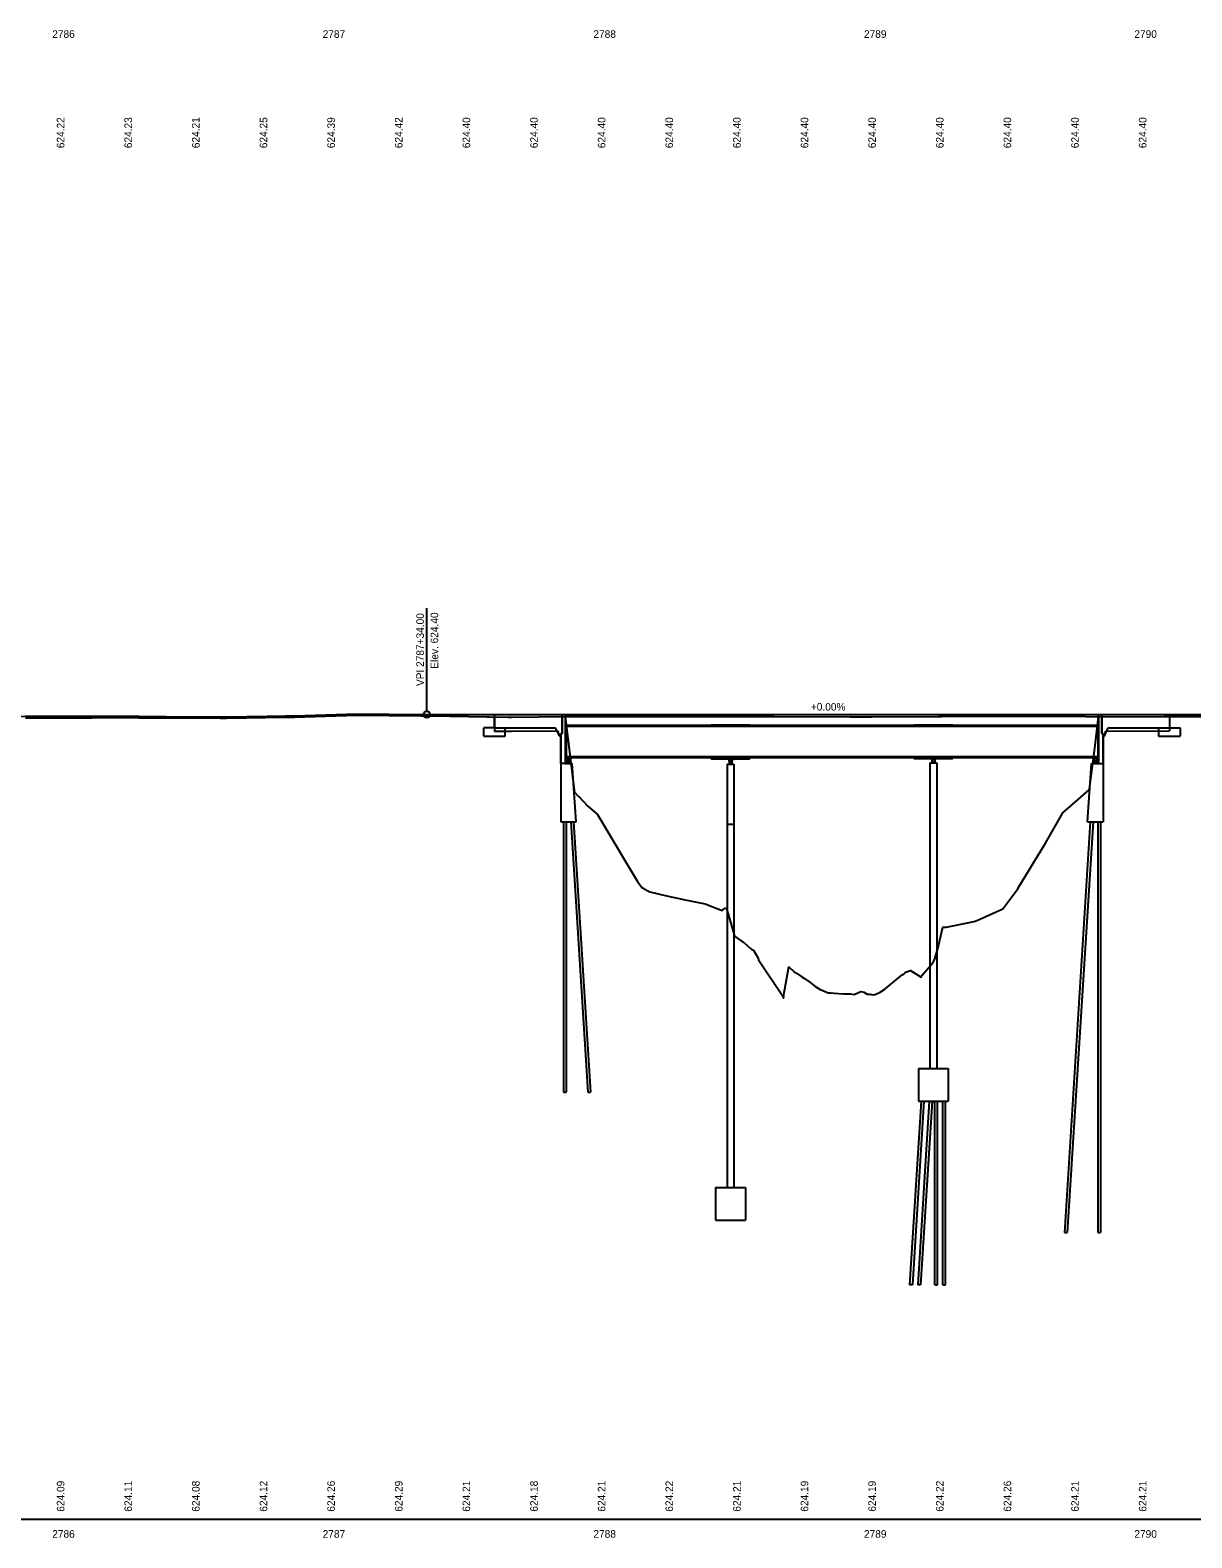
# Model space of a CAD drawing. Extents: x 2376379 to 2383101, y 559608 to 561720.
# Drawn here: x 2379153 to 2379582, y 560612 to 561170 of the extents above; entities that cross this region are included whole.
import ezdxf

# ---------------------------------------------------------------- set-up
doc = ezdxf.new("R2010")
doc.units = 0
for name, color, linetype in [('AP_P_Airside', 7, 'Continuous'), ('BR_X_SV_Abut', 7, 'Continuous'), ('BR_X_SV_Shot_Marker', 7, 'Continuous'), ('DR_X_Ditch', 7, 'Continuous'), ('DR_X_Erosion_Control', 7, 'Continuous'), ('DR_X_Storm_Sewer', 7, 'Continuous'), ('DR_X_Text', 7, 'Continuous'), ('DT_X_Terrain_Ground_Line', 7, 'Continuous'), ('PV_X_Driveway', 7, 'Continuous'), ('SC_Scratch1', 7, 'Continuous'), ('SV_X_Control_Cells_Found', 7, 'Continuous'), ('SV_X_Text', 7, 'Continuous'), ('UT_X_Overhead_Electric', 7, 'Continuous')]:
    doc.layers.add(name, color=color, linetype=linetype)

msp = doc.modelspace()

# ---------------------------------------------------------------- linework, layer by layer
at = {"layer": 'AP_P_Airside'}
msp.add_line((2379299.62, 560918.13), (2379299.62, 560956.2), dxfattribs=at)
msp.add_circle((2379299.62, 560916.92), 1.21, dxfattribs=at)
at = {"layer": 'BR_X_SV_Abut'}
for p, q in [((2379351.45, 560900.73), (2379351.45, 560899.73)), ((2379352.28, 560900.73), (2379351.45, 560900.73)), ((2379352.28, 560900.73), (2379352.28, 560899.73)), ((2379411.28, 560900.51), (2379411.28, 560899.68)), ((2379412.45, 560900.51), (2379411.28, 560900.51)), ((2379412.45, 560900.51), (2379412.45, 560899.68)), ((2379486.27, 560900.66), (2379486.27, 560900.16)), ((2379487.44, 560900.66), (2379486.27, 560900.66)), ((2379487.44, 560900.66), (2379487.44, 560900.16)), ((2379546.44, 560900.73), (2379546.44, 560899.73)), ((2379547.27, 560900.73), (2379546.44, 560900.73)), ((2379547.27, 560900.73), (2379547.27, 560899.73)), ((2379352.28, 560899.73), (2379351.45, 560899.73)), ((2379351.49, 560899.73), (2379351.49, 560898.84)), ((2379352.24, 560898.84), (2379351.49, 560898.84)), ((2379352.24, 560899.73), (2379352.24, 560898.84)), ((2379412.45, 560899.68), (2379411.28, 560899.68)), ((2379411.33, 560899.68), (2379411.33, 560898.52)), ((2379412.41, 560898.52), (2379411.33, 560898.52)), ((2379412.41, 560899.68), (2379412.41, 560898.52)), ((2379487.44, 560900.16), (2379486.27, 560900.16)), ((2379486.32, 560900.16), (2379486.32, 560899)), ((2379487.4, 560899), (2379486.32, 560899)), ((2379487.4, 560900.16), (2379487.4, 560899)), ((2379547.27, 560899.73), (2379546.44, 560899.73)), ((2379546.48, 560899.73), (2379546.48, 560898.84)), ((2379547.23, 560898.84), (2379546.48, 560898.84)), ((2379547.23, 560899.73), (2379547.23, 560898.84))]:
    msp.add_line(p, q, dxfattribs=at)
at = {"layer": 'DR_X_Ditch'}
for p, q in [((2379351.12, 560912.99), (2379351.12, 560900.99)), ((2379351.12, 560912.99), (2379547.62, 560912.99)), ((2379351.12, 560912.65), (2379547.62, 560912.65)), ((2379404.7, 560912.99), (2379404.7, 560913.14)), ((2379404.7, 560913.14), (2379419.03, 560913.14)), ((2379404.7, 560912.99), (2379404.7, 560913.14)), ((2379419.03, 560912.99), (2379419.03, 560913.14)), ((2379419.03, 560912.99), (2379419.03, 560913.14)), ((2379479.69, 560913.14), (2379494.02, 560913.14)), ((2379479.69, 560912.99), (2379479.69, 560913.14)), ((2379494.02, 560912.99), (2379494.02, 560913.14)), ((2379547.62, 560912.99), (2379547.62, 560900.99)), ((2379351.12, 560901.33), (2379547.62, 560901.33)), ((2379351.12, 560900.99), (2379547.62, 560900.99)), ((2379404.7, 560900.82), (2379404.7, 560900.99)), ((2379404.7, 560900.82), (2379419.03, 560900.82)), ((2379419.03, 560900.82), (2379419.03, 560900.99)), ((2379479.69, 560900.82), (2379479.69, 560900.99)), ((2379479.69, 560900.82), (2379494.02, 560900.82)), ((2379494.02, 560900.82), (2379494.02, 560900.99))]:
    msp.add_line(p, q, dxfattribs=at)
at = {"layer": 'DR_X_Storm_Sewer'}
for p, q in [((2379324.62, 560911.92), (2379324.62, 560916.92)), ((2379574.12, 560916.92), (2379574.12, 560911.92)), ((2379324.62, 560911.92), (2379347.2, 560911.92)), ((2379348.62, 560909.08), (2379347.2, 560911.92)), ((2379550.11, 560909.08), (2379551.53, 560911.92)), ((2379551.53, 560911.92), (2379574.12, 560911.92)), ((2379348.62, 560909.08), (2379349.12, 560909.08)), ((2379549.62, 560909.08), (2379550.11, 560909.08))]:
    msp.add_line(p, q, dxfattribs=at)
at = {"layer": 'DR_X_Text'}
for p, q in [((2379404.7, 560900.51), (2379404.7, 560900.68)), ((2379404.7, 560900.68), (2379419.03, 560900.68)), ((2379404.7, 560900.51), (2379419.03, 560900.51)), ((2379419.03, 560900.51), (2379419.03, 560900.68)), ((2379479.69, 560900.66), (2379479.69, 560900.82)), ((2379479.69, 560900.82), (2379494.02, 560900.82)), ((2379479.69, 560900.66), (2379494.02, 560900.66)), ((2379494.02, 560900.66), (2379494.02, 560900.82))]:
    msp.add_line(p, q, dxfattribs=at)
at = {"layer": 'DT_X_Terrain_Ground_Line'}
for p, q in [((2379320.62, 560908.92), (2379320.62, 560911.92)), ((2379324.62, 560911.92), (2379320.62, 560911.92)), ((2379328.62, 560908.92), (2379328.62, 560911.92)), ((2379570.12, 560911.92), (2379570.12, 560908.92)), ((2379574.12, 560911.92), (2379578.12, 560911.92)), ((2379578.12, 560911.92), (2379578.12, 560908.92)), ((2379320.62, 560908.92), (2379328.62, 560908.92)), ((2379570.12, 560908.92), (2379578.12, 560908.92))]:
    msp.add_line(p, q, dxfattribs=at)
at = {"layer": 'PV_X_Driveway'}
msp.add_lwpolyline([(2379151.22, 560915.64), (2379175.95, 560915.73), (2379192.51, 560915.75), (2379193.1, 560915.74), (2379198.76, 560915.73), (2379202.7, 560915.72), (2379223.33, 560915.59), (2379225.57, 560915.61), (2379247.27, 560915.89), (2379249.06, 560915.91), (2379250.63, 560915.94), (2379273.71, 560916.61), (2379297.46, 560916.44), (2379298.49, 560916.44), (2379301.44, 560916.39), (2379321.77, 560916.05), (2379322.73, 560916.04), (2379329.83, 560915.96), (2379330.86, 560915.96), (2379350.79, 560916.16), (2379354, 560889.89), (2379354.25, 560888), (2379354.29, 560888.01), (2379354.37, 560888.01), (2379355.61, 560886.73), (2379355.62, 560886.72), (2379359.07, 560882.98), (2379362.7, 560879.9), (2379366.85, 560872.9), (2379372.33, 560863.79), (2379377.43, 560855.16), (2379379.21, 560852.81), (2379379.32, 560852.78), (2379379.33, 560852.78), (2379379.71, 560852.55), (2379382.02, 560851.32), (2379387.77, 560849.98), (2379395.14, 560848.35), (2379402.54, 560846.83), (2379408.74, 560844.43), (2379409.78, 560845.22), (2379409.9, 560845.31), (2379410.33, 560845.17), (2379412.96, 560836.23), (2379413.38, 560834.98), (2379416.13, 560833), (2379416.73, 560832.71), (2379419.25, 560830.42), (2379419.58, 560830.11), (2379419.73, 560829.99), (2379420.33, 560829.73), (2379422.1, 560826.73), (2379422.23, 560826.23), (2379431.15, 560812.73), (2379431.47, 560812), (2379431.75, 560813.98), (2379433.44, 560823.52), (2379435.45, 560821.72), (2379436.21, 560821.21), (2379438.29, 560819.85), (2379439.21, 560819.22), (2379441.18, 560817.92), (2379443, 560816.41), (2379444.96, 560815.23), (2379446.03, 560814.82), (2379447.96, 560813.93), (2379449.07, 560813.94), (2379450.21, 560813.84), (2379453.66, 560813.56), (2379455.09, 560813.56), (2379456.23, 560813.57), (2379457.58, 560813.3), (2379460.08, 560814.4), (2379461.16, 560814.27), (2379462.36, 560813.44), (2379463.33, 560813.45), (2379463.95, 560813.33), (2379464.73, 560813.17), (2379465.63, 560813.44), (2379467.25, 560814.25), (2379468.86, 560815.33), (2379475.29, 560820.58), (2379475.72, 560820.73), (2379476.08, 560821.02), (2379476.4, 560821.42), (2379476.61, 560821.66), (2379478.38, 560822.22), (2379482.37, 560819.71), (2379482.75, 560820.46), (2379486.64, 560825.03), (2379487.25, 560826.2), (2379488.53, 560830.21), (2379490.34, 560838.26), (2379491.64, 560838.24), (2379501.98, 560840.33), (2379503.77, 560841.08), (2379512.59, 560845.06), (2379518.1, 560852.49), (2379518.12, 560852.52), (2379528.34, 560869.29), (2379534.7, 560880.6), (2379544.45, 560889.08), (2379544.55, 560889.17), (2379544.58, 560889.17), (2379544.61, 560889.42), (2379546.49, 560904.51), (2379547.93, 560916.1), (2379572.29, 560916.15), (2379573.41, 560916.15), (2379574.48, 560916.16), (2379598.49, 560916.15)], dxfattribs=at)
at = {"layer": 'SC_Scratch1'}
for p, q in [((2379349.62, 560909.92), (2379349.62, 560916.92)), ((2379350.87, 560898.84), (2379350.87, 560916.92)), ((2379547.87, 560898.84), (2379547.87, 560916.92)), ((2379549.12, 560909.92), (2379549.12, 560916.92)), ((2379349.12, 560898.84), (2379349.12, 560909.92)), ((2379349.12, 560909.92), (2379349.62, 560909.92)), ((2379549.12, 560909.92), (2379549.62, 560909.92)), ((2379549.62, 560898.84), (2379549.62, 560909.92)), ((2379350.87, 560898.84), (2379349.12, 560898.84)), ((2379547.87, 560898.84), (2379549.62, 560898.84))]:
    msp.add_line(p, q, dxfattribs=at)
at = {"layer": 'SV_X_Control_Cells_Found'}
for p, q in [((2379324.62, 560916.02), (2379324.62, 560910.68)), ((2379349.62, 560916.15), (2379349.62, 560909.82)), ((2379350.87, 560915.49), (2379350.87, 560898.84)), ((2379547.87, 560916.1), (2379547.87, 560898.84)), ((2379549.12, 560916.11), (2379549.12, 560909.77)), ((2379574.12, 560916.16), (2379574.12, 560910.83)), ((2379348.57, 560908.99), (2379348.12, 560910.8)), ((2379349.12, 560908.99), (2379348.57, 560908.99)), ((2379349.12, 560909.82), (2379349.12, 560877.26)), ((2379349.62, 560909.82), (2379349.12, 560909.82)), ((2379549.12, 560909.77), (2379549.62, 560909.77)), ((2379549.62, 560909.77), (2379549.62, 560877.26)), ((2379549.62, 560908.94), (2379550.12, 560908.94)), ((2379550.12, 560908.94), (2379550.58, 560910.78)), ((2379550.58, 560910.78), (2379574.12, 560910.83)), ((2379350.87, 560898.84), (2379353.37, 560898.84)), ((2379351.53, 560899.55), (2379351.53, 560898.84)), ((2379351.53, 560899.55), (2379352.2, 560899.55)), ((2379352.2, 560899.55), (2379352.2, 560898.84)), ((2379354.87, 560877.26), (2379353.37, 560898.84)), ((2379410.62, 560898.52), (2379410.62, 560741.92)), ((2379410.62, 560898.52), (2379413.12, 560898.52)), ((2379411.45, 560898.52), (2379411.45, 560899.31)), ((2379411.45, 560899.31), (2379412.28, 560899.31)), ((2379412.28, 560898.52), (2379412.28, 560899.31)), ((2379413.12, 560898.52), (2379413.12, 560741.92)), ((2379485.61, 560899), (2379485.61, 560785.92)), ((2379485.61, 560899), (2379488.11, 560899)), ((2379486.44, 560899), (2379486.44, 560899.46)), ((2379486.44, 560899.46), (2379487.27, 560899.46)), ((2379487.27, 560899), (2379487.27, 560899.46)), ((2379488.11, 560899), (2379488.11, 560785.92)), ((2379543.87, 560877.26), (2379545.37, 560898.84)), ((2379545.37, 560898.84), (2379547.87, 560898.84)), ((2379546.52, 560899.55), (2379546.52, 560898.84)), ((2379546.52, 560899.55), (2379547.19, 560899.55)), ((2379547.19, 560899.55), (2379547.19, 560898.84)), ((2379349.12, 560877.26), (2379354.87, 560877.26)), ((2379350.12, 560877.26), (2379350.12, 560777.26)), ((2379351.12, 560877.26), (2379351.12, 560777.26)), ((2379352.85, 560877.26), (2379359.1, 560777.26)), ((2379353.88, 560877.26), (2379360.13, 560777.26)), ((2379354.87, 560877.26), (2379354.87, 560877.26)), ((2379410.62, 560876.36), (2379413.12, 560876.36)), ((2379544.85, 560877.26), (2379535.35, 560725.26)), ((2379545.88, 560877.26), (2379536.38, 560725.26)), ((2379543.87, 560877.26), (2379549.62, 560877.26)), ((2379547.62, 560877.26), (2379547.62, 560725.26)), ((2379548.62, 560877.26), (2379548.62, 560725.26)), ((2379481.36, 560785.92), (2379481.36, 560773.92)), ((2379481.36, 560785.92), (2379492.36, 560785.92)), ((2379492.36, 560785.92), (2379492.36, 560773.92)), ((2379350.12, 560777.26), (2379351.12, 560777.26)), ((2379359.1, 560777.26), (2379360.13, 560777.26)), ((2379482.34, 560773.92), (2379478.09, 560705.92)), ((2379483.37, 560773.92), (2379479.12, 560705.92)), ((2379485.34, 560773.92), (2379481.09, 560705.92)), ((2379481.36, 560773.92), (2379492.36, 560773.92)), ((2379486.37, 560773.92), (2379482.12, 560705.92)), ((2379487.36, 560705.92), (2379487.36, 560773.92)), ((2379488.36, 560705.92), (2379488.36, 560773.92)), ((2379490.36, 560705.92), (2379490.36, 560773.92)), ((2379491.36, 560705.92), (2379491.36, 560773.92)), ((2379406.37, 560741.92), (2379406.37, 560729.92)), ((2379406.37, 560741.92), (2379417.37, 560741.92)), ((2379417.37, 560741.92), (2379417.37, 560729.92)), ((2379406.37, 560729.92), (2379417.37, 560729.92)), ((2379535.35, 560725.26), (2379536.38, 560725.26)), ((2379547.62, 560725.26), (2379548.62, 560725.26)), ((2379479.12, 560705.92), (2379478.09, 560705.92)), ((2379482.12, 560705.92), (2379481.09, 560705.92)), ((2379487.36, 560705.92), (2379488.36, 560705.92)), ((2379490.36, 560705.92), (2379491.36, 560705.92))]:
    msp.add_line(p, q, dxfattribs=at)
for points in [[(2379350.79, 560916.16), (2379355.61, 560916.16), (2379375.64, 560916.17), (2379376.26, 560916.18), (2379402.22, 560916.2), (2379403.42, 560916.19), (2379409.78, 560916.18), (2379427.31, 560916.14), (2379427.89, 560916.14), (2379456.09, 560916.03), (2379456.23, 560916.02), (2379456.39, 560916.02), (2379463.95, 560916.07), (2379488.71, 560916.19), (2379489.96, 560916.2), (2379503.75, 560916.28), (2379509.27, 560916.3), (2379514.92, 560916.35), (2379515.19, 560916.35), (2379515.21, 560916.35), (2379515.67, 560916.35), (2379518.12, 560916.34), (2379530.19, 560916.27), (2379530.91, 560916.27), (2379543.21, 560916.15), (2379547.83, 560916.1), (2379547.93, 560916.1)], [(2379348.12, 560910.8), (2379330.86, 560910.62), (2379329.83, 560910.63), (2379324.62, 560910.68)]]:
    msp.add_lwpolyline(points, dxfattribs=at)
at = {"layer": 'SV_X_Text'}
msp.add_line((2378765.62, 560619.32), (2380329.61, 560619.32), dxfattribs=at)
at = {"layer": 'UT_X_Overhead_Electric'}
msp.add_line((2379299.62, 560916.92), (2379590.62, 560916.92), dxfattribs=at)
for points in [[(2379240.62, 560916.3), (2379247.27, 560916.39), (2379250.63, 560916.44), (2379273.71, 560917.11), (2379297.46, 560916.94), (2379298.49, 560916.94), (2379299.62, 560916.92)], [(2379193.12, 560916.24), (2379175.95, 560916.23), (2379151.22, 560916.14), (2379147.75, 560916.11), (2379138.93, 560916.2), (2379124.24, 560916.33), (2379099.25, 560916.49), (2379084.76, 560916.57), (2379075.73, 560916.62), (2379048.26, 560916.44), (2379046.54, 560916.42), (2379043.12, 560916.38)], [(2379193.12, 560916.24), (2379203.29, 560916.22), (2379223.33, 560916.09), (2379225.57, 560916.11), (2379240.62, 560916.3)]]:
    msp.add_lwpolyline(points, dxfattribs=at)

# ---------------------------------------------------------------- texts
at = {"layer": 'AP_P_Airside'}
for s, p in [('VPI 2787+34.00', (2379298.53, 560927.44)), ('Elev. 624.40', (2379303.82, 560933.86))]:
    msp.add_text(s, height=2.8, rotation=90, dxfattribs=at).set_placement(p)
msp.add_text('+0.00%', height=2.8, dxfattribs=at).set_placement((2379441.57, 560918.36))
at = {"layer": 'BR_X_SV_Shot_Marker'}
for s, p in [('2786', (2379161.14, 561167.19)), ('2787', (2379261.09, 561167.19)), ('2788', (2379361.18, 561167.19)), ('2789', (2379461.2, 561167.19)), ('2790', (2379561.16, 561167.19)), ('2786', (2379161.14, 560612.42)), ('2787', (2379261.09, 560612.42)), ('2788', (2379361.18, 560612.42)), ('2789', (2379461.2, 560612.42)), ('2790', (2379561.16, 560612.42))]:
    msp.add_text(s, height=2.8, dxfattribs=at).set_placement(p)
for s, p in [('624.09', (2379165.62, 560622.05)), ('624.11', (2379190.62, 560622.05)), ('624.08', (2379215.62, 560622.05)), ('624.12', (2379240.62, 560622.05)), ('624.26', (2379265.62, 560622.05)), ('624.29', (2379290.62, 560622.05)), ('624.21', (2379315.62, 560622.05)), ('624.18', (2379340.62, 560622.05)), ('624.21', (2379365.62, 560622.05)), ('624.22', (2379390.62, 560622.05)), ('624.21', (2379415.62, 560622.05)), ('624.19', (2379440.62, 560622.05)), ('624.19', (2379465.62, 560622.05)), ('624.22', (2379490.62, 560622.05)), ('624.26', (2379515.62, 560622.05)), ('624.21', (2379540.62, 560622.05)), ('624.21', (2379565.62, 560622.05))]:
    msp.add_text(s, height=2.8, rotation=90, dxfattribs=at).set_placement(p)
at = {"layer": 'DR_X_Erosion_Control'}
for s, p in [('624.22', (2379165.62, 561126.37)), ('624.23', (2379190.62, 561126.37)), ('624.21', (2379215.62, 561126.37)), ('624.25', (2379240.62, 561126.37)), ('624.39', (2379265.62, 561126.37)), ('624.42', (2379290.62, 561126.37)), ('624.40', (2379315.62, 561126.37)), ('624.40', (2379340.62, 561126.37)), ('624.40', (2379365.62, 561126.37)), ('624.40', (2379390.62, 561126.37)), ('624.40', (2379415.62, 561126.37)), ('624.40', (2379440.62, 561126.37)), ('624.40', (2379465.62, 561126.37)), ('624.40', (2379490.62, 561126.37)), ('624.40', (2379515.62, 561126.37)), ('624.40', (2379540.62, 561126.37)), ('624.40', (2379565.62, 561126.37))]:
    msp.add_text(s, height=2.8, rotation=90, dxfattribs=at).set_placement(p)

doc.saveas('drawing.dxf')
